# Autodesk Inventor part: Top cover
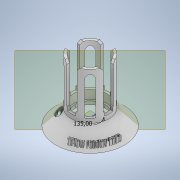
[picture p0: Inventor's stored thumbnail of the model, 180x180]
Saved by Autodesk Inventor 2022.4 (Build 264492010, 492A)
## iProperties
Created: 2021-04
Part Number: Top cover
Material: Generic
Document SubType Name: Modeling
Designer: tmass
Density: 1 g/cm^3
Appearance: Default
Author: tmass
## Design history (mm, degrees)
sketch "Sketch1"
  geometry: C1 r 35 at (0, 0); C2 r 47 at (0, 0); 1 further point
  constraints: 2 centre point, 2 coincident
  dimensions: "d40" = 94 diameter of C2; "d52" = 70 diameter of C1
extrude "Extrusion1" new body sketch "Sketch1" distance "d2" = 5; taper "d3" = 0 deg
workplane "Work Plane1"
sketch "Sketch5"
  geometry: C1 r 33 at (0, 0); C2 r 30 at (0, 0); C3 r 38 at (0, 0); 1 further point
  constraints: 3 centre point, 3 coincident
  dimensions: "d11" = 66 diameter of C1; "d12" = 60 diameter of C2; "d13" = 5 radial gap between concentric circles of C1 C3
extrude "Extrusion3" cut sketch "Sketch5" extent not by distance; stored distance "d14" = 0; taper "d15" = 0 deg
sketch "Sketch6"
  geometry: C1 r 32 at (0, 0); C2 r 29 at (0, 0); 1 further point
  constraints: 2 centre point, 2 coincident
  dimensions: "d16" = 64 diameter of C1; "d17" = 58 diameter of C2
extrude "Extrusion4" join sketch "Sketch6" stored distance "d18" = 2; taper "d19" = 0 deg
sketch "Sketch7"
  geometry: C1 r 37 at (0, 0); C2 r 32 at (0, 0) reference; 1 further point
  constraints: 1 centre point, 1 coincident
  dimensions: "d22" = 5 radial gap between concentric circles of C2 C1
extrude "Extrusion5" join sketch "Sketch7" distance "d23" = 100; taper "d24" = 0 deg; dims "d25" = 6.5, "d26" = 0
sketch "Sketch12"
  geometry: L1 (23.5, 8)-(23.5, -8); L2 (23.5, -8)-(91.5, -8); L3 (106.5, 32)-(106.5, -32) reference; L4 (8.5, 30)-(8.5, -30) reference; L5 (-21.3, 0)-(127.8, 0) reference; L6 (98.5, 2)-(91.5, 8); L7 (98.5, -2)-(91.5, -8); L8 (91.5, 8)-(23.5, 8); L9 (98.5, -2)-(98.5, 2); 3 further points
  constraints: 12 end point, 2 parallel, 1 horizontal, 1 midpoint, 1 perpendicular
  dimensions: "d49" = 15 distance between parallel lines of L4 L1; "d50" = 0 distance from line of point (64.782, 0) L5; "d51" = 16 distance of L1.start L1.end; "d98" = 2 distance from line of L5 L7.start; "d102" = 8 distance between parallel lines of L9 L3; "d110" = 8 distance from line of L2 point (64.782, 0); "d111" = 68 distance of L1.end L2.end; "d112" = 68 distance of L6.end L1.start (= d111); "d113" = 2 distance of point (98.5, 0) L6.start
extrude "Extrusion6" cut sketch "Sketch12" extent not by distance; stored distance "d43" = 0; taper "d44" = 0 deg
pattern_circular "Circular Pattern2" dims angle "d46" = 360 deg
sketch "Sketch13"
  geometry: C1 r 30 at (0, 0) reference; C2 r 45.75 at (0, 0); C3 r 41.25 at (0, 0); 1 further point
  constraints: 2 centre point, 2 coincident
  dimensions: "d54" = 82.5 diameter of C3; "d138" = 4.5 radial gap between concentric circles of C2 C3
extrude "Extrusion7" cut sketch "Sketch13" distance "d55" = 4; taper "d56" = 0 deg
sketch "Sketch14"
  geometry: L1 (5, 47)-(-14.871, 66.871); L2 (-14.871, 66.871)-(-14.871, 61.871); L3 (0, 47)-(5, 47) reference; L4 (0, 47)-(5, 47); L5 (-14.871, 61.871)-(0, 47); L6 (-19.568, 0)-(14.051, 0) reference; L7 (5, 47)-(15, 37); L8 (5, 37)-(106.5, 37) reference; L9 (5, 37)-(5, 47); L10 (5, 37)-(5, -37) reference; L11 (5, 37)-(15, 37); 3 further points
  constraints: 14 end point, 3 perpendicular, 3 point on line, 1 collinear, 1 parallel
  dimensions: "d60" = 5 distance of L3.start L3.end (derived); "d61" = 5 distance of L2.end L1.end; "d62" = 5 distance of L1.start L4.start
revolve "Revolution3" sketch "Sketch14" stored, may be unused: angle "d63" = 360 deg
sketch "Sketch17"
  geometry: L1 (122.59, 10)-(30.5, 10); L2 (30.5, 10)-(30.5, -10); L3 (30.5, -10)-(122.59, -10); L4 (122.59, -10)-(122.59, 10); L5 (122.59, 10)-(30.5, -10); L6 (30.5, 10)-(122.59, -10); L7 (106.5, 32)-(106.5, 10); L8 (15.5, 30)-(15.5, -30); L9 (-19.5, 0)-(117, 0); L10 (106.5, 15)-(101.5, 10); L11 (106.5, -15)-(101.5, -10); L12 (106.5, 10)-(106.5, -10); L13 (106.5, -10)-(106.5, -32); L14 (106.5, 32)-(106.5, -32) reference; 3 further points
  constraints: 26 end point, 8 point on line, 2 midpoint, 2 parallel, 1 horizontal, 1 perpendicular
  dimensions: "d81" = 15 distance between parallel lines of L8 L2; "d82" = 0 distance from line of point (76.545, 0) L9; "d83" = 20 distance of L1.end L2.end; "d103" = 5 distance of L10.start L7.end; "d104" = 5 distance of L7.end L10.end; "d106" = 5 distance of L12.end L11.end; "d107" = 5 distance of L12.end L11.start
extrude "Extrusion8" cut sketch "Sketch17" extent not by distance; stored distance "d85" = 0; taper "d86" = 0 deg
pattern_circular "Circular Pattern4" dims angle "d88" = 360 deg
sketch "Sketch20"
  geometry: A1 r 61.871 centre (0, 0) between (61.871, 0) and (0, 61.871) reference; A2 r 61.871 centre (0, 0) between (61.871, 0) and (0, 61.871); 1 further point
  constraints: 4 point on circle, 1 centre point, 1 concentric, 1 other
emboss "Emboss4" sketch "Sketch20" dims "d10" = 6.5, "d108" = 2, "d109" = 0
sketch "Sketch21"
  geometry: L1 (31.297, -27.184)-(41.224, -13.153); L2 (0, 0)-(42.164, 0); C1 r 29 at (0, 0); C2 r 41.25 at (0, 0); C3 r 29 at (0, 0) reference; C4 r 5.5 at (34.5, 0); C5 r 5.5 at (0, -34.5); C6 r 5.5 at (-34.5, 0); C7 r 5.5 at (0, 34.5); C8 r 29 at (0, 0) reference; 10 further points
  constraints: 6 centre point, 4 end point, 2 coincident, 2 tangent, 1 horizontal, 1 point on line, 11 other
  dimensions: "d121" = 11 diameter of C4; "d124" = 360 deg dimension on point (0, 0) C4.centre (derived)
extrude "Extrusion9" cut sketch "Sketch21" distance "d126" = 3.5; taper "d127" = 0 deg
workplane "Work Plane5"
sketch "Sketch23"
  geometry: L1 (0, 20.891)-(0, -20.602); L2 (15.615, -15.47)-(-14.811, 14.955); 2 further points
  constraints: 4 end point, 1 midpoint, 1 point on line, 1 vertical
  dimensions: "d130" = 135 deg angle of L1 L2
workplane "Work Plane4"
sketch "Sketch24"
  geometry: L1 (88.852, -14.271)-(58.98, 15.6) reference; L2 (58.98, 15.6)-(50.98, 0.927); L3 (50.98, 0.6)-(50.98, 7.1) reference; L4 (58.98, 15.6)-(74.831, 15.6); L5 (74.831, 15.6)-(66.303, -0.041); L6 (50.98, 0.927)-(47.848, -4.817); L7 (47.848, -4.817)-(63.699, -4.817); L8 (63.699, -4.817)-(66.435, 0.2); L9 (74.831, 15.6)-(47.848, -4.817); 4 further points
  constraints: 14 end point, 2 collinear, 2 horizontal, 2 point on line, 1 parallel, 1 other
revolve "Revolution5" sketch "Sketch24" stored, may be unused: angle "d137" = 90 deg
pattern_circular "Circular Pattern5" dims angle "d140" = 360 deg
body "Solid1"
other parameters: "sa_0" = 4
